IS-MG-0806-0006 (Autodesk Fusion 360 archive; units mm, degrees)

design "IS-MG-0806-0006" references "LED", "8 ports ethernet", "USB Type C Port (SMD Type) (1)", "Digitus_DN-651107_LAN-Switch", "DIP Switch", "SFP SLOT", "3M Screw", "6 holes POWER"
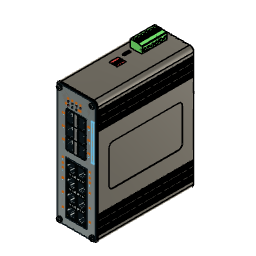
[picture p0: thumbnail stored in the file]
sketch "Sketch1" plane through (0, 0, 0) normal (0, 1, 0) x axis (1, 0, 0)
  line L1 (45, 0) -> (5, 0)
  line L2 (50, -145) -> (50, -5)
  line L3 (5, -150) -> (45, -150)
  line L4 (0, -5) -> (0, -145)
  arc A1 centre (5, -145) radius 5 clockwise from (5, -150) to (0, -145)
  arc A2 centre (45, -145) radius 5 clockwise from (50, -145) to (45, -150)
  arc A3 centre (5, -5) radius 5 clockwise from (0, -5) to (5, 0)
  arc A4 centre (45, -5) radius 5 clockwise from (45, 0) to (50, -5)
  point P1 (0, 0)
  point P2 (0, 0)
  point P4 (0, -150)
  point P3 (50, 0)
  horizontal L1
  vertical L2
  horizontal L3
  vertical L4
  coincident P1 P2
  coincident P4 L3
  coincident P4 L4
  tangent L3 A1
  tangent L4 A1
  tangent L2 A2
  tangent L3 A2
  equal A1 A2
  coincident P2 L1
  coincident P2 L4
  tangent L1 A3
  tangent L4 A3
  equal A1 A3
  coincident P3 L1
  coincident P3 L2
  tangent L1 A4
  tangent L2 A4
  equal A1 A4
  dimension "d1" distance P2 P3 = 50
  dimension "d2" distance P2 P4 = 150
  dimension "d3" radius A1 = 5
extrude "Extrude1" new body sketch "Sketch1" along normal blind 120
sketch "Sketch2" plane through (0, 0, 0) normal (0, -1, 0) x axis (1, 0, 0)
  line L1 (5, 150) -> (45, 150)
  line L2 (0, 5) -> (0, 145)
  line L3 (45, 0) -> (5, 0)
  line L4 (50, 145) -> (50, 5)
  line L5 (45, 1.5) -> (5, 1.5)
  line L6 (48.5, 145) -> (48.5, 5)
  line L7 (5, 148.5) -> (45, 148.5)
  line L8 (1.5, 5) -> (1.5, 145)
  line L9 (45, 0) -> (5, 0)
  line L10 (50, 145) -> (50, 5)
  line L11 (5, 150) -> (45, 150)
  line L12 (0, 5) -> (0, 145)
  arc A1 centre (45, 145) radius 5 clockwise from (45, 150) to (50, 145)
  arc A2 centre (5, 145) radius 5 clockwise from (0, 145) to (5, 150)
  arc A3 centre (5, 5) radius 5 clockwise from (5, 0) to (0, 5)
  arc A4 centre (45, 5) radius 5 clockwise from (50, 5) to (45, 0)
  arc A5 centre (45, 5) radius 3.5 clockwise from (48.5, 5) to (45, 1.5)
  arc A6 centre (45, 145) radius 3.5 clockwise from (45, 148.5) to (48.5, 145)
  arc A7 centre (5, 145) radius 3.5 clockwise from (1.5, 145) to (5, 148.5)
  arc A8 centre (5, 5) radius 3.5 clockwise from (5, 1.5) to (1.5, 5)
  arc A9 centre (45, 5) radius 5 clockwise from (50, 5) to (45, 0)
  arc A10 centre (45, 145) radius 5 clockwise from (45, 150) to (50, 145)
  arc A11 centre (5, 145) radius 5 clockwise from (0, 145) to (5, 150)
  arc A12 centre (5, 5) radius 5 clockwise from (5, 0) to (0, 5)
  dimension "d6" = -1.5
  dimension "d7" distance L3 = 0
extrude "Extrude2" cut sketch "Sketch2" against normal blind 1.5
sketch "Sketch3" plane through (0, 120, 0) normal (0, 1, 0) x axis (-1, 0, 0)
  line L1 (-50, 5) -> (-50, 145)
  line L2 (-5, 0) -> (-45, 0)
  line L3 (0, 145) -> (0, 5)
  line L4 (-45, 150) -> (-5, 150)
  line L5 (-5, 1.5) -> (-45, 1.5)
  line L6 (-1.5, 145) -> (-1.5, 5)
  line L7 (-45, 148.5) -> (-5, 148.5)
  line L8 (-48.5, 5) -> (-48.5, 145)
  line L9 (-5, 0) -> (-45, 0)
  line L10 (0, 145) -> (0, 5)
  line L11 (-45, 150) -> (-5, 150)
  line L12 (-50, 5) -> (-50, 145)
  arc A1 centre (-45, 145) radius 5 clockwise from (-50, 145) to (-45, 150)
  arc A2 centre (-45, 5) radius 5 clockwise from (-45, 0) to (-50, 5)
  arc A3 centre (-5, 5) radius 5 clockwise from (0, 5) to (-5, 0)
  arc A4 centre (-5, 145) radius 5 clockwise from (-5, 150) to (0, 145)
  arc A5 centre (-5, 5) radius 3.5 clockwise from (-1.5, 5) to (-5, 1.5)
  arc A6 centre (-5, 145) radius 3.5 clockwise from (-5, 148.5) to (-1.5, 145)
  arc A7 centre (-45, 145) radius 3.5 clockwise from (-48.5, 145) to (-45, 148.5)
  arc A8 centre (-45, 5) radius 3.5 clockwise from (-45, 1.5) to (-48.5, 5)
  arc A9 centre (-5, 5) radius 5 clockwise from (0, 5) to (-5, 0)
  arc A10 centre (-5, 145) radius 5 clockwise from (-5, 150) to (0, 145)
  arc A11 centre (-45, 145) radius 5 clockwise from (-50, 145) to (-45, 150)
  arc A12 centre (-45, 5) radius 5 clockwise from (-45, 0) to (-50, 5)
  dimension "d10" = -1.5
  dimension "d11" distance L2 = 0
extrude "Extrude3" cut sketch "Sketch3" against normal blind 1.5
sketch "Sketch4" plane through (0, 1.5, 0) normal (0, -1, 0) x axis (1, 0, 0)
  line L1 (1.5, 145) -> (1.5, 5)
  line L2 (45, 148.5) -> (5, 148.5)
  line L3 (48.5, 5) -> (48.5, 145)
  line L4 (5, 1.5) -> (45, 1.5)
  line L5 (45, 0) -> (5, 0)
  line L6 (50, 145) -> (50, 5)
  line L7 (5, 150) -> (45, 150)
  line L8 (0, 5) -> (0, 145)
  line L9 (25, 75) -> (25, 148.5)
  line L10 (25, 75) -> (1.5, 75)
  line L11 (0.75, 9) -> (0, 9)
  line L12 (0.75, 10.5) -> (0.75, 9)
  line L13 (0, 10.5) -> (0.75, 10.5)
  line L14 (0, 9) -> (0, 10.5)
  line L15 (0, 12.75) -> (0.75, 12.75)
  line L16 (0, 11.25) -> (0, 12.75)
  line L17 (0.75, 11.25) -> (0, 11.25)
  line L18 (0.75, 12.75) -> (0.75, 11.25)
  line L19 (0, 15) -> (0.75, 15)
  line L20 (0, 13.5) -> (0, 15)
  line L21 (0.75, 13.5) -> (0, 13.5)
  line L22 (0.75, 15) -> (0.75, 13.5)
  line L23 (0.75, 19.25) -> (0, 19.25)
  line L24 (0.75, 20.75) -> (0.75, 19.25)
  line L25 (0, 19.25) -> (0, 20.75)
  line L26 (0.75, 18.5) -> (0.75, 17)
  line L27 (0, 21.5) -> (0, 23)
  line L28 (0, 23) -> (0.75, 23)
  line L29 (0.75, 21.5) -> (0, 21.5)
  line L30 (0, 20.75) -> (0.75, 20.75)
  line L31 (0, 18.5) -> (0.75, 18.5)
  line L32 (0, 17) -> (0, 18.5)
  line L33 (0.75, 17) -> (0, 17)
  line L34 (0.75, 23) -> (0.75, 21.5)
  line L35 (0.75, 27.25) -> (0, 27.25)
  line L36 (0.75, 28.75) -> (0.75, 27.25)
  line L37 (0, 27.25) -> (0, 28.75)
  line L38 (0.75, 26.5) -> (0.75, 25)
  line L39 (0, 29.5) -> (0, 31)
  line L40 (0, 31) -> (0.75, 31)
  line L41 (0.75, 29.5) -> (0, 29.5)
  line L42 (0, 28.75) -> (0.75, 28.75)
  line L43 (0, 26.5) -> (0.75, 26.5)
  line L44 (0, 25) -> (0, 26.5)
  line L45 (0.75, 25) -> (0, 25)
  line L46 (0.75, 31) -> (0.75, 29.5)
  line L47 (0.75, 141) -> (0, 141)
  line L48 (0, 138.75) -> (0, 137.25)
  line L49 (0, 133) -> (0, 131.5)
  line L50 (0, 120.5) -> (0, 119)
  line L51 (0, 128.5) -> (0, 127)
  line L52 (0, 121.25) -> (0.75, 121.25)
  line L53 (0.75, 125) -> (0, 125)
  line L54 (0.75, 128.5) -> (0, 128.5)
  line L55 (0.75, 129.25) -> (0.75, 130.75)
  line L56 (0.75, 120.5) -> (0, 120.5)
  line L57 (0.75, 131.5) -> (0.75, 133)
  line L58 (0.75, 123.5) -> (0.75, 125)
  line L59 (0, 122.75) -> (0, 121.25)
  line L60 (0.75, 138.75) -> (0, 138.75)
  line L61 (0, 130.75) -> (0, 129.25)
  line L62 (0.75, 130.75) -> (0, 130.75)
  line L63 (0, 139.5) -> (0.75, 139.5)
  line L64 (0.75, 133) -> (0, 133)
  line L65 (0.75, 127) -> (0.75, 128.5)
  line L66 (0.75, 137.25) -> (0.75, 138.75)
  line L67 (0, 137.25) -> (0.75, 137.25)
  line L68 (0.75, 119) -> (0.75, 120.5)
  line L69 (0, 125) -> (0, 123.5)
  line L70 (0.75, 122.75) -> (0, 122.75)
  line L71 (0.75, 139.5) -> (0.75, 141)
  line L72 (0, 129.25) -> (0.75, 129.25)
  line L73 (0, 123.5) -> (0.75, 123.5)
  line L74 (0, 119) -> (0.75, 119)
  line L75 (0, 141) -> (0, 139.5)
  line L76 (0.75, 135) -> (0.75, 136.5)
  line L77 (0.75, 136.5) -> (0, 136.5)
  line L78 (0, 136.5) -> (0, 135)
  line L79 (0, 131.5) -> (0.75, 131.5)
  line L80 (0, 135) -> (0.75, 135)
  line L81 (0.75, 121.25) -> (0.75, 122.75)
  line L82 (0, 127) -> (0.75, 127)
  line L83 (49.25, 127) -> (49.25, 128.5)
  line L84 (50, 122.75) -> (50, 121.25)
  line L85 (49.25, 121.25) -> (49.25, 122.75)
  line L86 (50, 127) -> (49.25, 127)
  line L87 (49.25, 129.25) -> (49.25, 130.75)
  line L88 (49.25, 137.25) -> (49.25, 138.75)
  line L89 (50, 119) -> (49.25, 119)
  line L90 (50, 139.5) -> (49.25, 139.5)
  line L91 (50, 123.5) -> (49.25, 123.5)
  line L92 (50, 136.5) -> (50, 135)
  line L93 (50, 135) -> (49.25, 135)
  line L94 (50, 120.5) -> (50, 119)
  line L95 (50, 133) -> (50, 131.5)
  line L96 (49.25, 119) -> (49.25, 120.5)
  line L97 (50, 128.5) -> (50, 127)
  line L98 (49.25, 131.5) -> (49.25, 133)
  line L99 (49.25, 120.5) -> (50, 120.5)
  line L100 (49.25, 133) -> (50, 133)
  line L101 (50, 138.75) -> (50, 137.25)
  line L102 (50, 125) -> (50, 123.5)
  line L103 (49.25, 139.5) -> (49.25, 141)
  line L104 (49.25, 135) -> (49.25, 136.5)
  line L105 (49.25, 136.5) -> (50, 136.5)
  line L106 (50, 137.25) -> (49.25, 137.25)
  line L107 (49.25, 125) -> (50, 125)
  line L108 (50, 121.25) -> (49.25, 121.25)
  line L109 (49.25, 138.75) -> (50, 138.75)
  line L110 (50, 130.75) -> (50, 129.25)
  line L111 (49.25, 141) -> (50, 141)
  line L112 (49.25, 130.75) -> (50, 130.75)
  line L113 (50, 129.25) -> (49.25, 129.25)
  line L114 (50, 131.5) -> (49.25, 131.5)
  line L115 (49.25, 122.75) -> (50, 122.75)
  line L116 (50, 141) -> (50, 139.5)
  line L117 (49.25, 128.5) -> (50, 128.5)
  line L118 (49.25, 123.5) -> (49.25, 125)
  line L119 (50, 18.5) -> (49.25, 18.5)
  line L120 (49.25, 19.25) -> (50, 19.25)
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  point P22 (25, 148.5)
  point P23 (1.5, 75)
  point P25 (0, 9)
  point P74 (0, 141)
  point P26 (0.75, 9)
  point P81 (0.75, 141)
  point P27 (0.75, 10.5)
  point P77 (0.75, 139.5)
  point P28 (0, 10.5)
  point P69 (0, 139.5)
  point P29 (0.75, 12.75)
  point P67 (0.75, 137.25)
  point P30 (0, 12.75)
  point P68 (0, 137.25)
  point P31 (0, 11.25)
  point P89 (0, 138.75)
  point P32 (0.75, 11.25)
  point P86 (0.75, 138.75)
  point P33 (0.75, 15)
  point P79 (0.75, 135)
  point P34 (0, 15)
  point P94 (0, 135)
  point P35 (0, 13.5)
  point P90 (0, 136.5)
  point P36 (0.75, 13.5)
  point P65 (0.75, 136.5)
  point P37 (0.75, 17)
  point P95 (0.75, 133)
  point P38 (0, 19.25)
  point P96 (0, 130.75)
  point P39 (0.75, 19.25)
  point P75 (0.75, 130.75)
  point P40 (0.75, 20.75)
  point P72 (0.75, 129.25)
  point P41 (0.75, 23)
  point P73 (0.75, 127)
  point P42 (0, 20.75)
  point P62 (0, 129.25)
  point P43 (0, 23)
  point P61 (0, 127)
  point P44 (0.75, 18.5)
  point P63 (0.75, 131.5)
  point P45 (0, 21.5)
  point P66 (0, 128.5)
  point P46 (0, 17)
  point P70 (0, 133)
  point P47 (0.75, 21.5)
  point P91 (0.75, 128.5)
  point P48 (0, 18.5)
  point P84 (0, 131.5)
  point P49 (0.75, 25)
  point P83 (0.75, 125)
  point P50 (0, 27.25)
  point P76 (0, 122.75)
  point P51 (0.75, 27.25)
  point P78 (0.75, 122.75)
  point P52 (0.75, 28.75)
  point P88 (0.75, 121.25)
  point P53 (0.75, 31)
  point P87 (0.75, 119)
  point P54 (0, 28.75)
  point P82 (0, 121.25)
  point P55 (0, 31)
  point P80 (0, 119)
  point P56 (0.75, 26.5)
  point P85 (0.75, 123.5)
  point P57 (0, 29.5)
  point P93 (0, 120.5)
  point P58 (0, 25)
  point P92 (0, 125)
  point P59 (0.75, 29.5)
  point P71 (0.75, 120.5)
  point P60 (0, 26.5)
  point P64 (0, 123.5)
  point P5 (1.5, 145)
  point P123 (48.5, 145)
  point P21 (0, 145)
  point P106 (50, 145)
  point P145 (50, 9)
  point P140 (49.25, 9)
  point P158 (49.25, 10.5)
  point P153 (50, 10.5)
  point P166 (49.25, 12.75)
  point P170 (50, 12.75)
  point P169 (50, 11.25)
  point P167 (49.25, 11.25)
  point P151 (49.25, 15)
  point P152 (50, 15)
  point P154 (50, 13.5)
  point P161 (49.25, 13.5)
  point P143 (49.25, 17)
  point P141 (50, 19.25)
  point P137 (49.25, 19.25)
  point P160 (49.25, 20.75)
  point P155 (49.25, 23)
  point P156 (50, 20.75)
  point P162 (50, 23)
  point P159 (49.25, 18.5)
  point P148 (50, 21.5)
  point P149 (50, 17)
  point P147 (49.25, 21.5)
  point P165 (50, 18.5)
  point P168 (49.25, 25)
  point P150 (50, 27.25)
  point P157 (49.25, 27.25)
  point P163 (49.25, 28.75)
  point P164 (49.25, 31)
  point P144 (50, 28.75)
  point P136 (50, 31)
  point P146 (49.25, 26.5)
  point P139 (50, 29.5)
  point P142 (50, 25)
  point P138 (49.25, 29.5)
  point P135 (50, 26.5)
  point P97 (50, 127)
  point P100 (50, 129.25)
  point P98 (49.25, 131.5)
  point P99 (50, 123.5)
  point P105 (49.25, 136.5)
  point P114 (50, 128.5)
  point P103 (49.25, 137.25)
  point P102 (50, 137.25)
  point P101 (50, 139.5)
  point P110 (50, 133)
  point P115 (49.25, 120.5)
  point P111 (49.25, 129.25)
  point P112 (49.25, 127)
  point P104 (50, 141)
  point P113 (49.25, 130.75)
  point P132 (50, 122.75)
  point P109 (49.25, 139.5)
  point P131 (49.25, 122.75)
  point P108 (49.25, 135)
  point P134 (50, 119)
  point P117 (49.25, 141)
  point P133 (50, 121.25)
  point P130 (49.25, 125)
  point P124 (50, 131.5)
  point P125 (49.25, 123.5)
  point P121 (49.25, 138.75)
  point P127 (49.25, 119)
  point P128 (49.25, 121.25)
  point P118 (50, 138.75)
  point P120 (50, 136.5)
  point P122 (49.25, 128.5)
  point P119 (50, 125)
  point P116 (50, 120.5)
  point P126 (50, 135)
  point P107 (49.25, 133)
  point P129 (50, 130.75)
  midpoint L2 P22
  perpendicular L2 L9
  midpoint L1 P23
  perpendicular L9 L10
  horizontal L11
  vertical L12
  horizontal L13
  vertical L14
  coincident L8 P25
  symmetric L10 P25 P74
  symmetric L10 P26 P81
  symmetric L10 P27 P77
  symmetric L10 P28 P69
  symmetric L10 P29 P67
  symmetric L10 P30 P68
  symmetric L10 P31 P89
  symmetric L10 P32 P86
  symmetric L10 P33 P79
  symmetric L10 P34 P94
  symmetric L10 P35 P90
  symmetric L10 P36 P65
  symmetric L10 P37 P95
  symmetric L10 P38 P96
  symmetric L10 P39 P75
  symmetric L10 P40 P72
  symmetric L10 P41 P73
  symmetric L10 P42 P62
  symmetric L10 P43 P61
  symmetric L10 P44 P63
  symmetric L10 P45 P66
  symmetric L10 P46 P70
  symmetric L10 P47 P91
  symmetric L10 P48 P84
  symmetric L10 P49 P83
  symmetric L10 P50 P76
  symmetric L10 P51 P78
  symmetric L10 P52 P88
  symmetric L10 P53 P87
  symmetric L10 P54 P82
  symmetric L10 P55 P80
  symmetric L10 P56 P85
  symmetric L10 P57 P93
  symmetric L10 P58 P92
  symmetric L10 P59 P71
  symmetric L10 P60 P64
  symmetric P5 L9 P123
  symmetric P21 L9 P106
  symmetric L9 P25 P145
  symmetric L9 P26 P140
  symmetric L9 P27 P158
  symmetric L9 P28 P153
  symmetric L9 P29 P166
  symmetric L9 P30 P170
  symmetric L9 P31 P169
  symmetric L9 P32 P167
  symmetric L9 P33 P151
  symmetric L9 P34 P152
  symmetric L9 P35 P154
  symmetric L9 P36 P161
  symmetric L9 P37 P143
  symmetric L9 P38 P141
  symmetric L9 P39 P137
  symmetric L9 P40 P160
  symmetric L9 P41 P155
  symmetric L9 P42 P156
  symmetric L9 P43 P162
  symmetric L9 P44 P159
  symmetric L9 P45 P148
  symmetric L9 P46 P149
  symmetric L9 P47 P147
  symmetric L9 P48 P165
  symmetric L9 P49 P168
  symmetric L9 P50 P150
  symmetric L9 P51 P157
  symmetric L9 P52 P163
  symmetric L9 P53 P164
  symmetric L9 P54 P144
  symmetric L9 P55 P136
  symmetric L9 P56 P146
  symmetric L9 P57 P139
  symmetric L9 P58 P142
  symmetric L9 P59 P138
  symmetric L9 P60 P135
  symmetric L9 P61 P97
  symmetric L9 P62 P100
  symmetric L9 P63 P98
  symmetric L9 P64 P99
  symmetric L9 P65 P105
  symmetric L9 P66 P114
  symmetric L9 P67 P103
  symmetric L9 P68 P102
  symmetric L9 P69 P101
  symmetric L9 P70 P110
  symmetric L9 P71 P115
  symmetric L9 P72 P111
  symmetric L9 P73 P112
  symmetric L9 P74 P104
  symmetric L9 P75 P113
  symmetric L9 P76 P132
  symmetric L9 P77 P109
  symmetric L9 P78 P131
  symmetric L9 P79 P108
  symmetric L9 P80 P134
  symmetric L9 P81 P117
  symmetric L9 P82 P133
  symmetric L9 P83 P130
  symmetric L9 P84 P124
  symmetric L9 P85 P125
  symmetric L9 P86 P121
  symmetric L9 P87 P127
  symmetric L9 P88 P128
  symmetric L9 P89 P118
  symmetric L9 P90 P120
  symmetric L9 P91 P122
  symmetric L9 P92 P119
  symmetric L9 P93 P116
  symmetric L9 P94 P126
  symmetric L9 P95 P107
  symmetric L9 P96 P129
  dimension "d14" distance P25 P28 = 1.5
  dimension "d15" distance P27 P28 = 0.75
  dimension "d24" distance L10 L40 = 44
  dimension "d18" R-Pattern1-uDistance = 0
  dimension "d19" R-Pattern1-vDistance = 4.5
  dimension "d22" R-Pattern2-uDistance = 0
  dimension "d23" R-Pattern2-vDistance = 16
extrude "Extrude4" cut sketch "Sketch4" against normal blind 125
sketch "Sketch5" plane through (0, 0, 0) normal (0, -1, 0) x axis (1, 0, 0)
  line L1 (1.5, 5) -> (1.5, 145)
  line L2 (45, 1.5) -> (5, 1.5)
  line L3 (48.5, 145) -> (48.5, 5)
  line L4 (5, 148.5) -> (45, 148.5)
  line L5 (25, 75) -> (25, 148.5)
  line L6 (25, 75) -> (1.5, 75)
  line L7 (37.9, 10.2) -> (12.1, 10.2)
  line L8 (37.9, 74) -> (37.9, 10.2)
  line L9 (12.1, 74) -> (37.9, 74)
  line L10 (12.1, 10.2) -> (12.1, 74)
  line L11 (36.2, 126.5) -> (13.8, 126.5)
  line L12 (36.95, 83.75) -> (36.95, 125.75)
  line L13 (13.8, 83) -> (36.2, 83)
  line L14 (13.05, 125.75) -> (13.05, 83.75)
  arc A1 centre (5, 5) radius 3.5 clockwise from (5, 1.5) to (1.5, 5)
  arc A2 centre (45, 5) radius 3.5 clockwise from (48.5, 5) to (45, 1.5)
  arc A3 centre (45, 145) radius 3.5 clockwise from (45, 148.5) to (48.5, 145)
  arc A4 centre (5, 145) radius 3.5 clockwise from (1.5, 145) to (5, 148.5)
  circle C1 centre (15.05, 130.5) radius 0.75
  circle C2 centre (20.05, 130.5) radius 0.75
  circle C3 centre (25.05, 130.5) radius 0.75
  circle C4 centre (15.05, 134.5) radius 0.75
  circle C5 centre (20.05, 134.5) radius 0.75
  circle C6 centre (25.05, 134.5) radius 0.75
  circle C7 centre (30.05, 134.5) radius 0.75
  circle C8 centre (5, 145) radius 1.5
  circle C9 centre (45, 145) radius 1.5
  circle C10 centre (5, 5) radius 1.5
  circle C11 centre (45, 5) radius 1.5
  arc A5 centre (13.8, 83.75) radius 0.75 clockwise from (13.8, 83) to (13.05, 83.75)
  arc A6 centre (36.2, 83.75) radius 0.75 clockwise from (36.95, 83.75) to (36.2, 83)
  arc A7 centre (36.2, 125.75) radius 0.75 clockwise from (36.2, 126.5) to (36.95, 125.75)
  arc A8 centre (13.8, 125.75) radius 0.75 clockwise from (13.05, 125.75) to (13.8, 126.5)
  point P14 (25, 148.5)
  point P15 (1.5, 75)
  point P23 (13.05, 83)
  point P22 (36.95, 83)
  point P21 (13.05, 126.5)
  point P17 (12.1, 10.2)
  point P20 (12.1, 74)
  point P19 (37.9, 74)
  point P24 (15.05, 130.5)
  midpoint L4 P14
  perpendicular L4 L5
  midpoint L1 P15
  perpendicular L1 L6
  horizontal L7
  vertical L8
  horizontal L9
  vertical L10
  symmetric L5 L8 L10
  horizontal L11
  vertical L12
  horizontal L13
  vertical L14
  symmetric L5 L12 L14
  concentric A4 C8
  coincident P23 L13
  coincident P23 L14
  tangent L13 A5
  tangent L14 A5
  coincident P22 L12
  coincident P22 L13
  tangent L12 A6
  tangent L13 A6
  equal A5 A6
  tangent L11 A7
  tangent L12 A7
  equal A5 A7
  coincident P21 L11
  coincident P21 L14
  tangent L11 A8
  tangent L14 A8
  equal A5 A8
  dimension "d27" distance P17 P20 = 63.8
  dimension "d28" distance P19 P20 = 25.8
  dimension "d29" distance P22 P23 = 23.9
  dimension "d30" distance P21 P23 = 43.5
  dimension "d31" distance L6 L9 = 1
  dimension "d32" distance L6 L13 = 8
  dimension "d33" diameter C1 = 1.5
  dimension "d34" distance L11 P24 = 4
  dimension "d35" distance L14 P24 = 2
  dimension "d48" diameter C8 = 3
  dimension "d80" radius A5 = 0.75
  dimension "d38" R-Pattern1-uDistance = 10
  dimension "d39" R-Pattern1-vDistance = 0
  dimension "d42" R-Pattern2-uDistance = 0
  dimension "d43" R-Pattern2-vDistance = 4
  dimension "d46" R-Pattern3-uDistance = 15
  dimension "d47" R-Pattern3-vDistance = 0
  dimension "d51" R-Pattern4-uDistance = 40
  dimension "d52" R-Pattern4-vDistance = 0
  dimension "d55" R-Pattern5-uDistance = 0
  dimension "d56" R-Pattern5-vDistance = -140
extrude "Extrude5" cut sketch "Sketch5" profile of L5 L7 L8 L9 L10 L11 L12 L13 L14 C1 C2 C3 C4 C5 C6 C7 C8 C9 C10 C11 against normal blind 2
shell "Shell1" innerThickness 1
sketch "Sketch8" plane through (0, 0, 150) normal (0, 0, 1) x axis (-1, 0, 0)
  line L1 (-5, -118.5) -> (-45, -118.5)
  line L2 (-5, -1.5) -> (-5, -118.5)
  line L3 (-45, -1.5) -> (-5, -1.5)
  line L4 (-45, -118.5) -> (-45, -1.5)
  line L5 (-25, -60) -> (-25, -118.5)
  line L6 (-25, -60) -> (-5, -60)
  line L7 (-20, -109.5) -> (-11.4, -109.5)
  line L8 (-20, -79.5) -> (-20, -109.5)
  line L9 (-11.4, -79.5) -> (-20, -79.5)
  line L10 (-11.4, -109.5) -> (-11.4, -79.5)
  line L11 (-15.36, -76) -> (-14.65, -76)
  line L12 (-16.61, -68.31) -> (-16.61, -74.75)
  line L13 (-14.65, -67.06) -> (-15.36, -67.06)
  line L14 (-13.4, -74.75) -> (-13.4, -68.31)
  line L15 (-23.9, -62.06) -> (-13.9, -62.06)
  line L16 (-23.9, -51.06) -> (-23.9, -62.06)
  line L17 (-13.9, -51.06) -> (-23.9, -51.06)
  line L18 (-13.9, -62.06) -> (-13.9, -51.06)
  arc A1 centre (-14.65, -74.75) radius 1.25 clockwise from (-13.4, -74.75) to (-14.65, -76)
  arc A2 centre (-15.36, -74.75) radius 1.25 clockwise from (-15.36, -76) to (-16.61, -74.75)
  arc A3 centre (-14.65, -68.31) radius 1.25 clockwise from (-14.65, -67.06) to (-13.4, -68.31)
  arc A4 centre (-15.36, -68.31) radius 1.25 clockwise from (-16.61, -68.31) to (-15.36, -67.06)
  point P6 (-25, -118.5)
  point P7 (-5, -60)
  point P13 (-13.4, -76)
  point P15 (-13.4, -67.06)
  point P14 (-16.61, -67.06)
  point P9 (-11.4, -109.5)
  point P12 (-11.4, -79.5)
  point P10 (-20, -109.5)
  point P16 (-14.65, -76)
  point P28 (-13.9, -62.06)
  point P31 (-13.9, -51.06)
  point P30 (-23.9, -51.06)
  midpoint L1 P6
  perpendicular L1 L5
  midpoint L2 P7
  perpendicular L2 L6
  horizontal L7
  vertical L8
  horizontal L9
  vertical L10
  horizontal L11
  vertical L12
  horizontal L13
  vertical L14
  coincident P13 L11
  coincident P13 L14
  tangent L11 A1
  tangent L14 A1
  tangent L11 A2
  tangent L12 A2
  equal A1 A2
  coincident P15 L13
  coincident P15 L14
  tangent L13 A3
  tangent L14 A3
  equal A1 A3
  coincident P14 L12
  coincident P14 L13
  tangent L12 A4
  tangent L13 A4
  equal A1 A4
  horizontal L15
  vertical L16
  horizontal L17
  vertical L18
  dimension "d122" distance P9 P12 = 30
  dimension "d123" distance P9 P10 = 8.6
  dimension "d124" distance L5 L8 = 5
  dimension "d125" distance P6 L7 = 9
  dimension "d126" distance P13 P15 = 8.94
  dimension "d127" distance P14 P15 = 3.21
  dimension "d128" radius A1 = 1.25
  dimension "d129" distance L9 P16 = 3.5
  dimension "d130" distance L10 L14 = 2
  dimension "d131" distance P28 P31 = 11
  dimension "d132" distance P30 P31 = 10
  dimension "d133" distance L14 L18 = 0.5
  dimension "d134" distance L13 L15 = 5
extrude "Extrude6" cut sketch "Sketch8" profile of L6 L7 L8 L9 L10 L11 L12 L13 L14 A1 A2 A3 A4 L15 L16 L17 L18 against normal blind 2
component_insert "Component Insert1"
joint "Assemble1" alignAngle 0 alignOffsetX 0 alignOffsetY 0 alignOffsetZ 1.5
rectangular_pattern "00000000-0000-0000-0000-000000000000" uSpaceDistance 15 vSpaceDistance 0
rectangular_pattern "00000000-0000-0000-0000-000000000000" uSpaceDistance -4 vSpaceDistance 0
rectangular_pattern "00000000-0000-0000-0000-000000000000" uSpaceDistance 10 vSpaceDistance 0
component_insert "Component Insert2"
component_insert "Component Insert3"
position "Position1"
rectangular_pattern "00000000-0000-0000-0000-000000000000" uSpaceDistance 29 vSpaceDistance 0
component_insert "Component Insert4"
joint "Assemble2" alignAngle -90 alignOffsetX 0 alignOffsetY 0 alignOffsetZ 6
rectangular_pattern "00000000-0000-0000-0000-000000000000" uSpaceDistance 40 vSpaceDistance 0
rectangular_pattern "00000000-0000-0000-0000-000000000000" uSpaceDistance -140 vSpaceDistance 0
component_insert "Component Insert7"
position "Position2"
sketch "Sketch6" plane through (0, 0, 0) normal (0, -1, 0) x axis (1, 0, 0)
  dimension "d93" = 2
  dimension "d94" = 2
  dimension "d95" = 2
  dimension "d96" = 2
  dimension "d97" = 2
  dimension "d98" = 2
  dimension "d99" = 2
  dimension "d100" = 2
  dimension "d101" = 2
  dimension "d102" = 2
  dimension "d103" = 2
  dimension "d104" = 2
  dimension "d105" = 2
  dimension "d106" = 2
  dimension "d107" = 2
  dimension "d108" = 2
  dimension "d109" = 2
  dimension "d110" = 2
  dimension "d111" = 2
  dimension "d112" = 1
  dimension "d113" = 1
  dimension "d114" = 1
  dimension "d115" = 1
  dimension "d116" = 1
  dimension "d117" = 1
  dimension "d118" = 1
  dimension "d119" = 1
  dimension "d120" = 1
  dimension "d121" = 1
component_insert "Component Insert8"
component_insert "Component Insert9"
component_insert "Component Insert10"
decal "Decal1"
position "Position3"
sketch "Sketch9" plane through (50, 0, 0) normal (1, 0, 0) x axis (0, 1, 0)
  line L1 (118.5, 31) -> (1.5, 31)
  line L2 (118.5, 119) -> (118.5, 31)
  line L3 (1.5, 119) -> (118.5, 119)
  line L4 (1.5, 31) -> (1.5, 119)
  line L5 (60, 75) -> (60, 119)
  line L6 (60, 75) -> (1.5, 75)
  line L7 (100, 100) -> (20, 100)
  line L8 (105, 55) -> (105, 95)
  line L9 (20, 50) -> (100, 50)
  line L10 (15, 95) -> (15, 55)
  arc A1 centre (20, 55) radius 5 clockwise from (20, 50) to (15, 55)
  arc A2 centre (100, 55) radius 5 clockwise from (105, 55) to (100, 50)
  arc A3 centre (100, 95) radius 5 clockwise from (100, 100) to (105, 95)
  arc A4 centre (20, 95) radius 5 clockwise from (15, 95) to (20, 100)
  point P6 (60, 119)
  point P7 (1.5, 75)
  point P11 (15, 50)
  point P10 (105, 50)
  point P9 (15, 100)
  midpoint L3 P6
  perpendicular L3 L5
  midpoint L4 P7
  perpendicular L4 L6
  horizontal L7
  vertical L8
  horizontal L9
  vertical L10
  symmetric L6 L7 L9
  coincident P11 L9
  coincident P11 L10
  tangent L9 A1
  tangent L10 A1
  coincident P10 L8
  coincident P10 L9
  tangent L8 A2
  tangent L9 A2
  equal A1 A2
  tangent L7 A3
  tangent L8 A3
  equal A1 A3
  coincident P9 L7
  coincident P9 L10
  tangent L7 A4
  tangent L10 A4
  equal A1 A4
  dimension "d137" distance P9 P11 = 50
  dimension "d138" distance P10 P11 = 90
  dimension "d139" radius A1 = 5
extrude "Extrude7" cut sketch "Sketch9" profile of L5 L6 L7 L8 L9 L10 A1 A2 A3 A4 against normal blind 0.5
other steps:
joint_origin "JointOrigin1"
joint_origin "JointOrigin2"

design "LED"
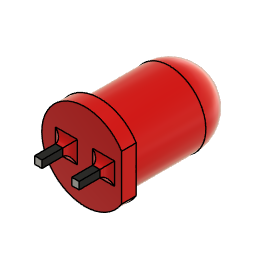
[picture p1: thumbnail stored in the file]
description: STEP AP214
part number: LED

design "8 ports ethernet"
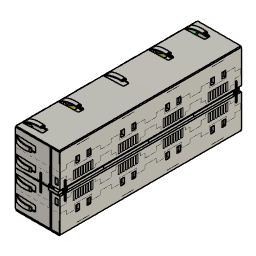
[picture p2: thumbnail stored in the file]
description: STEP AP214
part number: 8 ports ethernet

design "SFP SLOT"
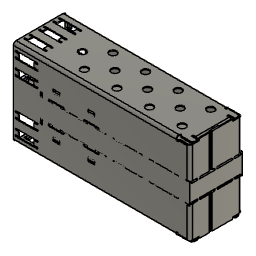
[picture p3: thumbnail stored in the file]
description: STEP AP214
part number: SFP SLOT

design "USB Type C Port (SMD Type) (1)"
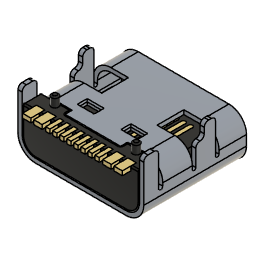
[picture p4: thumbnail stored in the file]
description: STEP AP214
part number: USB Type C Port (SMD Type) (1)

design "6 holes POWER"
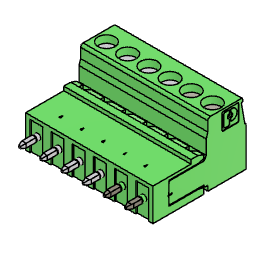
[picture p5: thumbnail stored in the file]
description: STEP AP214
part number: POWER

design "3M Screw"
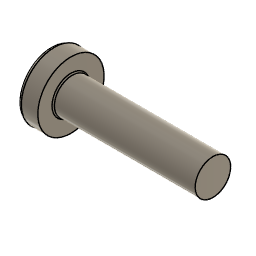
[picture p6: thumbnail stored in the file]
description: STEP AP214
part number: 3M Screw

design "DIP Switch"
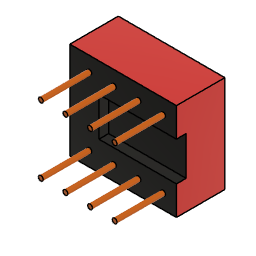
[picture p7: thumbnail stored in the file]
description: STEP AP214
part number: DIP Switch

design "Digitus_DN-651107_LAN-Switch"
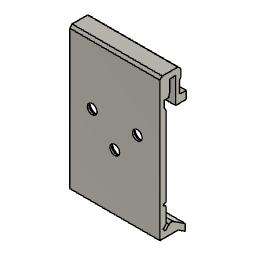
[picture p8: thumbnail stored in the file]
description: STEP AP214
part number: Digitus_DN-651107_LAN-Switch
